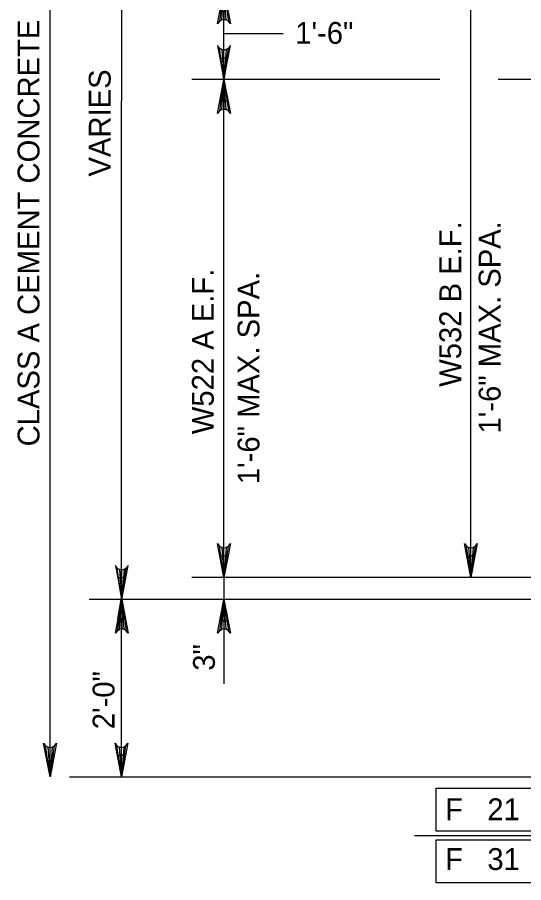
# Model space of a CAD drawing. Extents: x 638255 to 640306, y 296059 to 298435.
# Drawn here: x 639837.5 to 639907, y 297581.9 to 297700.8 of the extents above; entities that cross this region are included whole.
import ezdxf

# ---------------------------------------------------------------- set-up
doc = ezdxf.new("R2010")
doc.units = 0
doc.layers.add('Level 3', color=7, linetype='Continuous')
doc.layers.add('Level 4', color=7, linetype='Continuous')

msp = doc.modelspace()

# ---------------------------------------------------------------- linework, layer by layer
at = {"layer": 'Level 3'}
msp.add_line((639865.83, 297698.54), (639873.96, 297698.54), dxfattribs=at)
at = {"layer": 'Level 4'}
for p, q in [((639841.95, 297596.43), (639841.95, 297757.84)), ((639851.75, 297757.84), (639851.75, 297689.33)), ((639899.73, 297623.85), (639899.73, 297705.92)), ((639865.83, 297695.19), (639865.83, 297701.61)), ((639865.24, 297692.24), (639861.41, 297692.24)), ((639895.47, 297692.24), (639861.41, 297692.24)), ((639865.83, 297623.85), (639865.83, 297692.24)), ((639961.04, 297692.24), (639903.48, 297692.24)), ((639851.75, 297623.76), (639851.75, 297689.33)), ((639922.63, 297623.85), (639861.41, 297623.84)), ((639865.83, 297623.84), (639865.83, 297609.23)), ((639920.49, 297623.85), (639890.33, 297623.85)), ((639930.7, 297620.82), (639847.33, 297620.82)), ((639897.09, 297620.82), (639861.41, 297620.82)), ((639851.75, 297596.43), (639851.75, 297618.14)), ((639865.83, 297617.87), (639865.83, 297614.92)), ((639844.62, 297596.43), (639931.32, 297596.43)), ((639894.96, 297589), (639894.96, 297594.9)), ((639894.96, 297594.9), (639913.87, 297594.9)), ((639913.87, 297589), (639894.96, 297589)), ((639892, 297588.38), (639943.86, 297588.38)), ((639894.96, 297587.8), (639913.87, 297587.8)), ((639894.96, 297581.9), (639894.96, 297587.8)), ((639913.87, 297581.9), (639894.96, 297581.9))]:
    msp.add_line(p, q, dxfattribs=at)
for points in [[(639865.83, 297704.55), (639866.7, 297699.9), (639866.45, 297700.26), (639866.14, 297700.44), (639865.83, 297700.5), (639865.52, 297700.44), (639865.2, 297700.26), (639864.96, 297699.9), (639865.83, 297704.55), (639865.2, 297700.26), (639865.52, 297700.44), (639865.83, 297704.55), (639865.83, 297700.5), (639866.14, 297700.44), (639865.83, 297704.55), (639866.45, 297700.26)], [(639865.83, 297692.24), (639866.7, 297696.89), (639866.45, 297696.53), (639866.14, 297696.35), (639865.83, 297696.29), (639865.52, 297696.35), (639865.2, 297696.53), (639864.96, 297696.89), (639865.83, 297692.24), (639865.2, 297696.53), (639865.52, 297696.35), (639865.83, 297692.24), (639865.83, 297696.29), (639866.14, 297696.35), (639865.83, 297692.24), (639866.45, 297696.53)], [(639865.83, 297692.24), (639866.7, 297687.59), (639866.45, 297687.95), (639866.14, 297688.13), (639865.83, 297688.18), (639865.52, 297688.13), (639865.2, 297687.95), (639864.96, 297687.59), (639865.83, 297692.24), (639865.2, 297687.95), (639865.52, 297688.13), (639865.83, 297692.24), (639865.83, 297688.18), (639866.14, 297688.13), (639865.83, 297692.24), (639866.45, 297687.95)], [(639865.83, 297623.85), (639864.96, 297628.5), (639865.2, 297628.14), (639865.52, 297627.95), (639865.83, 297627.9), (639866.14, 297627.95), (639866.45, 297628.14), (639866.7, 297628.5), (639865.83, 297623.85), (639866.45, 297628.14), (639866.14, 297627.95), (639865.83, 297623.85), (639865.83, 297627.9), (639865.52, 297627.95), (639865.83, 297623.85), (639865.2, 297628.14)], [(639899.73, 297623.85), (639898.86, 297628.5), (639899.11, 297628.14), (639899.42, 297627.95), (639899.73, 297627.9), (639900.04, 297627.95), (639900.35, 297628.14), (639900.6, 297628.5), (639899.73, 297623.85), (639900.35, 297628.14), (639900.04, 297627.95), (639899.73, 297623.85), (639899.73, 297627.9), (639899.42, 297627.95), (639899.73, 297623.85), (639899.11, 297628.14)], [(639851.79, 297620.82), (639852.67, 297625.47), (639852.42, 297625.11), (639852.11, 297624.93), (639851.79, 297624.87), (639851.48, 297624.93), (639851.17, 297625.11), (639850.92, 297625.47), (639851.79, 297620.82), (639851.17, 297625.11), (639851.48, 297624.93), (639851.79, 297620.82), (639851.79, 297624.87), (639852.11, 297624.93), (639851.79, 297620.82), (639852.42, 297625.11)], [(639851.79, 297620.82), (639852.67, 297616.17), (639852.42, 297616.52), (639852.11, 297616.71), (639851.79, 297616.76), (639851.48, 297616.71), (639851.17, 297616.52), (639850.92, 297616.17), (639851.79, 297620.82), (639851.17, 297616.52), (639851.48, 297616.71), (639851.79, 297620.82), (639851.79, 297616.76), (639852.11, 297616.71), (639851.79, 297620.82), (639852.42, 297616.52)], [(639865.83, 297620.82), (639866.7, 297616.17), (639866.45, 297616.52), (639866.14, 297616.71), (639865.83, 297616.76), (639865.52, 297616.71), (639865.2, 297616.52), (639864.96, 297616.17), (639865.83, 297620.82), (639865.2, 297616.52), (639865.52, 297616.71), (639865.83, 297620.82), (639865.83, 297616.76), (639866.14, 297616.71), (639865.83, 297620.82), (639866.45, 297616.52)], [(639841.95, 297596.43), (639841.07, 297601.08), (639841.32, 297600.72), (639841.63, 297600.54), (639841.95, 297600.49), (639842.26, 297600.54), (639842.57, 297600.72), (639842.82, 297601.08), (639841.95, 297596.43), (639842.57, 297600.72), (639842.26, 297600.54), (639841.95, 297596.43), (639841.95, 297600.49), (639841.63, 297600.54), (639841.95, 297596.43), (639841.32, 297600.72)], [(639851.75, 297596.43), (639850.88, 297601.08), (639851.13, 297600.72), (639851.44, 297600.54), (639851.75, 297600.49), (639852.06, 297600.54), (639852.37, 297600.72), (639852.62, 297601.08), (639851.75, 297596.43), (639852.37, 297600.72), (639852.06, 297600.54), (639851.75, 297596.43), (639851.75, 297600.49), (639851.44, 297600.54), (639851.75, 297596.43), (639851.13, 297600.72)]]:
    msp.add_lwpolyline(points, dxfattribs=at)
for points in [[(639865.34, 297695.19), (639866.32, 297695.19), (639865.83, 297692.24)], [(639865.34, 297689.29), (639866.32, 297689.29), (639865.83, 297692.24)], [(639865.34, 297626.79), (639866.32, 297626.79), (639865.83, 297623.85)], [(639899.24, 297626.79), (639900.22, 297626.79), (639899.73, 297623.85)], [(639852.24, 297623.76), (639851.26, 297623.76), (639851.75, 297620.82)], [(639852.24, 297618.14), (639851.26, 297618.14), (639851.75, 297621.08)], [(639865.34, 297617.87), (639866.32, 297617.87), (639865.83, 297620.82)], [(639852.24, 297599.38), (639851.26, 297599.38), (639851.75, 297596.43)]]:
    msp.add_lwpolyline(points, close=True, dxfattribs=at)

# ---------------------------------------------------------------- texts
at = {"layer": 'Level 3'}
for s, p in [('3"', (639864.58, 297611.02)), ('2\'-0"', (639850.8, 297602.98))]:
    msp.add_text(s, height=3, rotation=90, dxfattribs=at).set_placement(p)
at = {"layer": 'Level 4'}
for s, height, p in [('CLASS A CEMENT CONCRETE', 3.0001, (639840.5, 297641.84)), ('VARIES', 3, (639850.27, 297678.91)), ('W532 B E.F.', 3.0001, (639898.4, 297650.02)), ('1\'-6" MAX. SPA.', 3.0001, (639903.8, 297643.61)), ('W522 A E.F.', 3.0001, (639864.43, 297643.51)), ('1\'-6" MAX. SPA.', 3.0001, (639870.7, 297636.65))]:
    msp.add_text(s, height=height, rotation=90, dxfattribs=at).set_placement(p)
for s, p in [('1\'-6"', (639875.61, 297697.14)), ('F   21', (639896.19, 297590.49)), ('F   31', (639896.19, 297583.65))]:
    msp.add_text(s, height=3, dxfattribs=at).set_placement(p)

doc.saveas('drawing.dxf')
